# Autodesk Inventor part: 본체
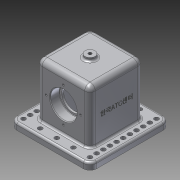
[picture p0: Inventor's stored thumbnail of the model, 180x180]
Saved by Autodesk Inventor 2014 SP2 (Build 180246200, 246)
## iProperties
Created: 2018-11
Part Number: 본체
Material: 알루미늄 6061
Document SubType Name: Modeling
Designer: 거성
Density: 2.71 g/cm^3
Appearance: 알루미늄 - 평지
Mass: 1019.13 g
Surface Area: 780.986 cm^2
Volume: 376.063 cm^3
Author: 거성
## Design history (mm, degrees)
sketch "스케치1"
  geometry: L1 (40, -40)-(-40, -40); L2 (-40, -40)-(-40, 40); L3 (-40, 40)-(40, 40); L4 (40, 40)-(40, -40); L5 (40, -40)-(-40, 40); L6 (-40, -40)-(40, 40); 1 further point
  constraints: 12 end point, 2 midpoint, 2 parallel, 1 horizontal, 1 perpendicular
  dimensions: "d0" = 80 distance of L2.end L3.end; "d1" = 80 distance of L1.end L2.end
extrude "돌출1" new body sketch "스케치1" distance "d2" = 90; taper "d3" = 0 deg
sketch "스케치2"
  geometry: L1 (-40, -40)-(40, -40) reference; L2 (40, -40)-(40, 40) reference; L3 (40, 40)-(-40, 40) reference; L4 (-40, 40)-(-40, -40) reference; L5 (-60, 60)-(60, 60); L6 (60, 60)-(60, -60); L7 (60, -60)-(-60, -60); L8 (-60, -60)-(-60, 60); L9 (-60, 60)-(60, -60); L10 (60, 60)-(-60, -60); 1 further point
  constraints: 12 end point, 2 midpoint, 2 parallel, 1 horizontal, 1 perpendicular
  dimensions: "d4" = 120 distance of L6.end L7.end; "d5" = 120 distance of L5.end L6.end
extrude "돌출2" join sketch "스케치2" distance "d6" = 10; taper "d7" = 0 deg
fillet "모깎기1" dims "d8" = 8
fillet "모깎기2" dims "d9" = 10
fillet "모깎기3" dims "d10" = 3
sketch "스케치3"
  geometry: L1 (50, -57)-(-50, -57) reference; L2 (57, 50)-(57, -50) reference; C1 r 3.3 at (-25, -50); C2 r 3.3 at (0, -50); C3 r 3.3 at (25, -50); A1 r 7 centre (-50, -50) between (-57, -50) and (-50, -57) reference; 11 further points
  constraints: 3 centre point, 1 coincident
  dimensions: "d41" = 6.6 diameter of C1; "d43" = 6.6 diameter of C2; "d45" = 6.6 diameter of C3; "d56" = 32 distance from line of C3.centre L2; "d57" = 7 distance from line of C3.centre L1; "d58" = 57 distance from line of C2.centre L2; "d59" = 7 distance from line of C2.centre L1; "d60" = 82 distance from line of C1.centre L2; "d61" = 7 distance from line of C1.centre L1; "d62" = 107 distance from line of point (-50, 40) L2; "d63" = 97 distance from line of point (-50, 40) L1; "d64" = 107 distance from line of point (-50, 30) L2; "d65" = 87 distance from line of point (-50, 30) L1; "d66" = 107 distance from line of point (-50, 20) L2; "d67" = 77 distance from line of point (-50, 20) L1; "d68" = 107 distance from line of point (-50, 10) L2; "d69" = 67 distance from line of point (-50, 10) L1; "d70" = 107 distance from line of point (-50, 0) L2; "d71" = 57 distance from line of point (-50, 0) L1; "d72" = 107 distance from line of point (-50, -10) L2; "d73" = 47 distance from line of point (-50, -10) L1; "d74" = 107 distance from line of point (-50, -20) L2; "d75" = 37 distance from line of point (-50, -20) L1; "d76" = 107 distance from line of point (-50, -30) L2; "d77" = 27 distance from line of point (-50, -30) L1; "d78" = 107 distance from line of point (-50, -40) L2; "d79" = 17 distance from line of point (-50, -40) L1
hole "구멍1" sketch "스케치3" diameter "d80" = 6.6; stored, may be unused: countersink angle "d84" = 90 deg, drill point angle "d86" = 118 deg; dims "d81" = 6, "d82" = 4, "d83" = 2, "d85" = 8
sketch "스케치4"
  geometry: A1 r 7 centre (-50, 50) between (-50, 57) and (-57, 50) reference; 2 further points
  constraints: 1 coincident
hole "구멍2" sketch "스케치4" at (-50, 50) diameter "d87" = 6.6; stored, may be unused: countersink angle "d91" = 90 deg, drill point angle "d93" = 118 deg; dims "d88" = 6, "d89" = 4, "d90" = 2, "d92" = 8
hole "구멍3" sketch "스케치3" diameter "d94" = 6.6; stored, may be unused: countersink angle "d98" = 90 deg, drill point angle "d100" = 118 deg; dims "d95" = 6, "d96" = 4, "d97" = 2, "d99" = 8
sketch "스케치5"
  geometry: L1 (30, 23)-(-30, 23); L2 (-30, 23)-(-30, -23); L3 (-30, -23)-(30, -23); L4 (30, -23)-(30, 23); L5 (30, 23)-(-30, -23); L6 (-30, 23)-(30, -23); 1 further point
  constraints: 12 end point, 2 midpoint, 2 parallel, 1 horizontal, 1 perpendicular
  dimensions: "d101" = 60 distance of L3.end L2.end; "d102" = 46 distance of L2.end L1.end
extrude "돌출3" cut sketch "스케치5" distance "d103" = 80; taper "d104" = 0 deg
fillet "모깎기4" dims "d105" = 3
fillet "모깎기5" dims "d106" = 3
fillet "모깎기6" dims "d107" = 8
sketch "스케치6"
  geometry: L1 (0, 46.7)-(10, 46.7) reference; L2 (10, 46.7)-(10, 40) reference; L3 (10, 40)-(82, 40) reference; L4 (90, 32)-(90, -32) reference; L5 (82, -40)-(10, -40) reference; L6 (10, -40)-(10, -46.7) reference; L7 (10, -46.7)-(0, -46.7) reference; L8 (0, -46.7)-(0, -23) reference; L9 (0, -23)-(77, -23) reference; L10 (80, -20)-(80, 20) reference; L11 (77, 23)-(0, 23) reference; L12 (0, 23)-(0, 46.7) reference; L13 (10, 57)-(10, 53.3) reference; L14 (10, 53.3)-(0, 53.3) reference; L15 (0, 53.3)-(0, 60) reference; L16 (0, 60)-(7, 60) reference; L17 (7, -60)-(0, -60) reference; L18 (0, -60)-(0, -53.3) reference; L19 (0, -53.3)-(10, -53.3) reference; L20 (10, -53.3)-(10, -57) reference; L21 (0, 0)-(48, 0); L22 (48, 40)-(48, -40); L23 (48, 40)-(68, 40); L24 (68, 40)-(68, 26.6); L25 (67.4, 26)-(48, 26); A1 r 8 centre (82, 32) between (90, 32) and (82, 40) reference; A2 r 8 centre (82, -32) between (82, -40) and (90, -32) reference; A3 r 3 centre (77, -20) between (77, -23) and (80, -20) reference; A4 r 3 centre (77, 20) between (80, 20) and (77, 23) reference; A5 r 3 centre (7, 57) between (10, 57) and (7, 60) reference; A6 r 3 centre (7, -57) between (7, -60) and (10, -57) reference; A7 r 0.6 centre (67.4, 26.6) between (67.4, 26) and (68, 26.6); 1 further point
  constraints: 10 end point, 4 perpendicular, 4 point on line, 2 point on circle, 2 tangent, 1 centre point, 1 midpoint
  dimensions: "d108" = 48 distance of L21.end L21.start; "d110" = 80 distance of L22.start L22.end; "d111" = 14 distance of L23.end point (68, 26); "d112" = 0.6 radius of A7; "d113" = 40 diameter of L23.end L22
revolve "회전1" sketch "스케치6" stored, may be unused: angle "d114" = 90 deg
chamfer "모따기1" distance "d115" = 1; stored, may be unused: second distance "d116" = 2, angle "d117" = 45 deg
sketch "스케치7"
  geometry: C1 r 19.4 at (0, 0) reference; C2 r 16.5 at (0, 0); 1 further point
  constraints: 1 centre point, 1 coincident
  dimensions: "d118" = 33 diameter of C2
extrude "돌출4" cut sketch "스케치7" stored distance "d119" = 80; taper "d120" = 0 deg
sketch "스케치8"
  geometry: 1 further point
sketch "스케치9" dims "d121" = 52
  geometry: C1 r 21 at (32, 38) reference; 3 further points
  constraints: 1 coincident, 1 vertical alignment, 2 other
hole "구멍4" sketch "스케치9" at (32, 64) diameter "d122" = 3.242; stored, may be unused: countersink angle "d126" = 90 deg, drill point angle "d128" = 118 deg; dims "d123" = 8, "d124" = 4, "d125" = 2, "d127" = 10
node "작업 평면1"
sketch "스케치11"
  geometry: C1 r 7.5 at (0, 0); 1 further point
  constraints: 1 centre point, 1 coincident
  dimensions: "d133" = 15 diameter of C1
extrude "돌출5" join sketch "스케치11" stored distance "d134" = 25; taper "d135" = 0 deg
fillet "모깎기7" dims "d136" = 3
sketch "스케치12"
  geometry: C1 r 7.5 at (0, 0) reference; 1 further point
  constraints: 1 coincident
hole "구멍5" sketch "스케치12" at (0, 0) diameter "d137" = 4.917; stored, may be unused: countersink angle "d141" = 90 deg, drill point angle "d143" = 118 deg; dims "d138" = 40, "d139" = 4, "d140" = 2, "d142" = 10
sketch "스케치13"
  geometry: L1 (0, 72)-(64, 72) reference; L2 (-18, -10)-(82, -10) reference; L3 (92, -10)-(82, -10) reference; L4 (82, 0)-(-18, 0) reference; 3 further points
  constraints: 1 midpoint, 1 vertical alignment, 1 other
  dimensions: "d144" = 48 distance from line of L3 point (32, 38)
feature "엠보싱1" sketch "스케치13" dims "d0" = 80, "d1" = 80, "d145" = 0.5, "d146" = 0
fillet "모깎기8" dims "d147" = 3
node "솔리드1"
mirror "대칭1"
mirror "대칭2"
mirror "대칭3"
pattern_circular "원형 패턴1" dims angle "d130" = 360 deg
mirror "대칭4"
node "절단 모서리 투영1"
other parameters: "d132" = 5
